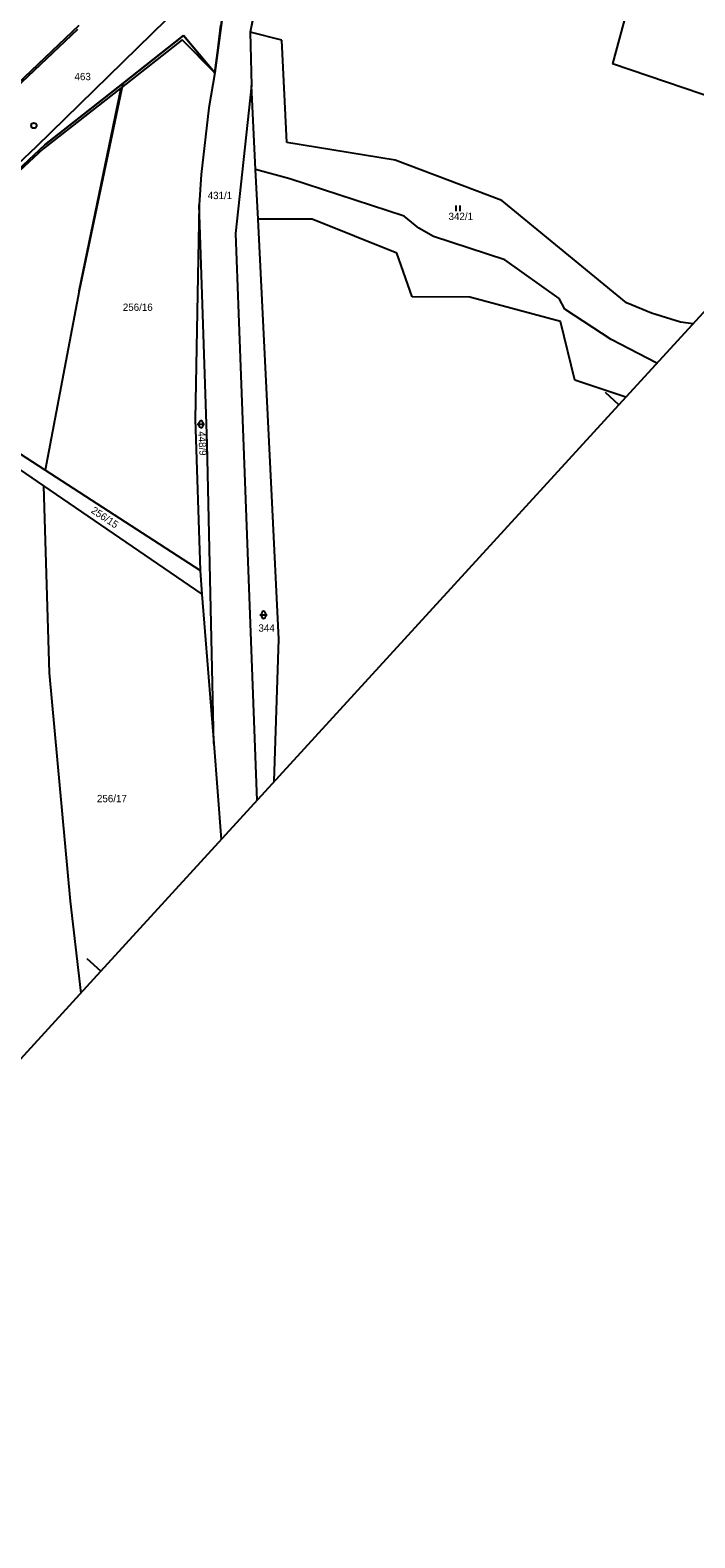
# Model space of a CAD drawing. Extents: x -678683 to -677755, y -1006946 to -1005971.
# Drawn here: x -678341.4 to -678159.6, y -1006946.3 to -1006533.9 of the extents above; entities that cross this region are included whole.
import ezdxf

# ---------------------------------------------------------------- set-up
doc = ezdxf.new("R2010")
doc.units = 0
for name, color, linetype in [('I_2_4_předběžný_vykres - SŽDC', 7, 'Continuous'), ('kilometráž - Vrstva 7', 7, 'Continuous'), ('koor - SSZT_nové', 7, 'Continuous'), ('MapaKN - Mladejov+Strelec_dosavani+nova_situace - Vrstva 1', 7, 'Continuous'), ('MapaKN - Mladejov+Strelec_dosavani+nova_situace - Vrstva 11', 7, 'Continuous'), ('MapaKN - Mladejov+Strelec_dosavani+nova_situace - Vrstva 18', 7, 'Continuous'), ('MapaKN - Mladejov+Strelec_dosavani+nova_situace - Vrstva 25', 7, 'Continuous'), ('MapaKN - původní vrstava 1', 7, 'Continuous'), ('ramy - Sekce lichá', 7, 'Continuous')]:
    doc.layers.add(name, color=color, linetype=linetype)

msp = doc.modelspace()

# ---------------------------------------------------------------- linework, layer by layer
at = {"layer": 'I_2_4_předběžný_vykres - SŽDC'}
for p, q in [((-678328.04, -1006532.61), (-678346.7, -1006550.29)), ((-678290.92, -1006545.55), (-678288.96, -1006531.28)), ((-678316.02, -1006548.44), (-678299.42, -1006535.34)), ((-678299.42, -1006535.34), (-678290.92, -1006545.55)), ((-678337.35, -1006565.27), (-678316.02, -1006548.44)), ((-678377.98, -1006603.23), (-678337.35, -1006565.27))]:
    msp.add_line(p, q, dxfattribs=at)
at = {"layer": 'kilometráž - Vrstva 7'}
msp.add_circle((-678340.38, -1006559.98), 0.75, dxfattribs=at)
at = {"layer": 'koor - SSZT_nové'}
msp.add_lwpolyline([(-678506.62, -1006791.94), (-678466.12, -1006753.23), (-678449.33, -1006728.75), (-678428.75, -1006695.61), (-678421.07, -1006681.97), (-678401.67, -1006635.24), (-678393.87, -1006623.11), (-678390.13, -1006617.26), (-678380, -1006603.76), (-678359.84, -1006584.7), (-678339.66, -1006565.68), (-678276.52, -1006503.93), (-678276.52, -1006503.93)], dxfattribs=at)
at = {"layer": 'MapaKN - Mladejov+Strelec_dosavani+nova_situace - Vrstva 1'}
for points in [[(-678157.68, -1006452.66), (-678182.07, -1006543.07)], [(-678281.26, -1006534.47), (-678280.85, -1006548.98)], [(-678272.58, -1006536.6), (-678281.26, -1006534.47)], [(-678271.19, -1006564.62), (-678272.58, -1006536.6)], [(-678152.85, -1006553.07), (-678182.07, -1006543.07)], [(-678290.92, -1006545.55), (-678292.51, -1006555.17)], [(-678280.85, -1006548.98), (-678285.21, -1006589.54)], [(-678279.72, -1006571.96), (-678280.85, -1006548.98)], [(-678292.51, -1006555.17), (-678294.65, -1006573.35)], [(-678241.53, -1006569.42), (-678271.19, -1006564.62)], [(-678212.35, -1006580.46), (-678241.53, -1006569.42)], [(-678294.65, -1006573.35), (-678295.16, -1006581.68)], [(-678279.05, -1006585.61), (-678279.72, -1006571.96)], [(-678270.4, -1006574.57), (-678279.72, -1006571.96)], [(-678239.14, -1006584.8), (-678270.4, -1006574.57)], [(-678295.16, -1006581.68), (-678296.26, -1006640.29)], [(-678292.98, -1006647), (-678295.16, -1006581.68)], [(-678178.25, -1006608.44), (-678212.35, -1006580.46)], [(-678264.24, -1006585.56), (-678279.05, -1006585.61)], [(-678275.33, -1006661.29), (-678279.05, -1006585.61)], [(-678241.07, -1006594.89), (-678264.24, -1006585.56)], [(-678235.04, -1006588.01), (-678239.14, -1006584.8)], [(-678285.21, -1006589.54), (-678284.39, -1006611.4)], [(-678231.06, -1006590.36), (-678235.04, -1006588.01)], [(-678211.53, -1006596.68), (-678231.06, -1006590.36)], [(-678236.94, -1006606.87), (-678241.07, -1006594.89)], [(-678196.66, -1006607.32), (-678211.53, -1006596.68)], [(-678327.99, -1006605.23), (-678337.28, -1006654.25)], [(-678221.13, -1006606.89), (-678236.94, -1006606.87)], [(-678196.29, -1006613.59), (-678221.13, -1006606.89)], [(-678195.19, -1006610.19), (-678196.66, -1006607.32)], [(-678182.49, -1006618.51), (-678195.19, -1006610.19)], [(-678171.46, -1006611.33), (-678178.25, -1006608.44)], [(-678163.55, -1006613.74), (-678171.46, -1006611.33)], [(-678284.39, -1006611.4), (-678279.37, -1006744.6)], [(-678192.43, -1006629.65), (-678196.29, -1006613.59)], [(-678160.06, -1006614.17), (-678163.55, -1006613.74)], [(-678169.95, -1006624.98), (-678182.49, -1006618.51)], [(-678178.44, -1006634.26), (-678192.43, -1006629.65)], [(-678337.28, -1006654.25), (-678352.67, -1006644.27)], [(-678296.26, -1006640.29), (-678294.91, -1006681.72)], [(-678354.06, -1006647.41), (-678337.76, -1006658.53)], [(-678291.19, -1006729.01), (-678292.98, -1006647)], [(-678294.91, -1006681.72), (-678337.28, -1006654.25)], [(-678337.76, -1006658.53), (-678294.43, -1006688.11)], [(-678337.76, -1006658.53), (-678336.21, -1006709.63)], [(-678273.4, -1006700.49), (-678275.33, -1006661.29)], [(-678294.91, -1006681.72), (-678294.43, -1006688.11)], [(-678294.43, -1006688.11), (-678291.19, -1006729.01)], [(-678274.62, -1006739.41), (-678273.4, -1006700.49)], [(-678336.21, -1006709.63), (-678330.47, -1006772.13)], [(-678291.19, -1006729.01), (-678289.11, -1006755.25)], [(-678330.47, -1006772.13), (-678327.57, -1006797.29)]]:
    msp.add_lwpolyline(points, dxfattribs=at)
at = {"layer": 'MapaKN - Mladejov+Strelec_dosavani+nova_situace - Vrstva 11'}
msp.add_line((-678316.02, -1006548.44), (-678327.99, -1006605.23), dxfattribs=at)
for points in [[(-678278.97, -1006523.26), (-678281.26, -1006534.47)], [(-678346.7, -1006550.29), (-678328.04, -1006532.61)], [(-678288.96, -1006531.28), (-678290.92, -1006545.55)], [(-678299.42, -1006535.34), (-678316.02, -1006548.44)], [(-678290.92, -1006545.55), (-678299.42, -1006535.34)], [(-678316.02, -1006548.44), (-678337.35, -1006565.27)], [(-678337.35, -1006565.27), (-678377.98, -1006603.23)]]:
    msp.add_lwpolyline(points, dxfattribs=at)
at = {"layer": 'MapaKN - Mladejov+Strelec_dosavani+nova_situace - Vrstva 25'}
for points in [[(-678224.83, -1006583.38), (-678224.83, -1006581.88)], [(-678223.79, -1006583.38), (-678223.79, -1006581.88)], [(-678295.67, -1006641.66), (-678293.67, -1006641.66)], [(-678295.17, -1006642.16), (-678295.17, -1006641.16)], [(-678294.17, -1006641.16), (-678294.17, -1006642.16)], [(-678278.54, -1006693.81), (-678276.54, -1006693.81)], [(-678278.04, -1006694.31), (-678278.04, -1006693.31)], [(-678277.04, -1006693.31), (-678277.04, -1006694.31)]]:
    msp.add_lwpolyline(points, dxfattribs=at)
for centre, start, end in [((-678294.67, -1006641.16), 0.101, 180.0014), ((-678294.67, -1006642.16), 180.1024, 0.0029), ((-678277.54, -1006693.31), 0.101, 180.0014), ((-678277.54, -1006694.31), 180.1024, 0.0029)]:
    msp.add_arc(centre, 0.5, start, end, dxfattribs=at)
at = {"layer": 'MapaKN - původní vrstava 1'}
for points in [[(-678279.33, -1006524.56), (-678281.26, -1006534.47)], [(-678289.35, -1006532.55), (-678290.92, -1006545.55)], [(-678328.43, -1006533.75), (-678347.15, -1006551.37)], [(-678299.82, -1006536.57), (-678316.46, -1006549.62)], [(-678290.92, -1006545.55), (-678299.82, -1006536.57)], [(-678316.46, -1006549.62), (-678337.85, -1006566.38)], [(-678327.99, -1006605.23), (-678316.46, -1006549.62)], [(-678337.85, -1006566.38), (-678378.6, -1006604.2)]]:
    msp.add_lwpolyline(points, dxfattribs=at)
at = {"layer": 'ramy - Sekce lichá'}
for p, q in [((-678180.35, -1006636.35), (-678038.61, -1006481.4)), ((-678180.35, -1006636.35), (-678184.04, -1006632.98)), ((-678322.09, -1006791.3), (-678180.35, -1006636.35)), ((-678322.09, -1006791.3), (-678325.78, -1006787.93)), ((-678463.83, -1006946.26), (-678322.09, -1006791.3))]:
    msp.add_line(p, q, dxfattribs=at)

# ---------------------------------------------------------------- texts
at = {"layer": 'MapaKN - Mladejov+Strelec_dosavani+nova_situace - Vrstva 18'}
for s, p in [('463', (-678329.26, -1006547.57)), ('431/1', (-678292.84, -1006580.1)), ('342/1', (-678226.96, -1006585.82)), ('256/16', (-678316.05, -1006610.67)), ('344', (-678278.96, -1006698.41)), ('256/17', (-678323.12, -1006745.05))]:
    msp.add_text(s, height=2, dxfattribs=at).set_placement(p)
for s, rotation, p in [('448/9', 273.6022, (-678295.48, -1006643.64)), ('256/15', 326.3026, (-678324.92, -1006665.71))]:
    msp.add_text(s, height=2, rotation=rotation, dxfattribs=at).set_placement(p)

doc.saveas('drawing.dxf')
